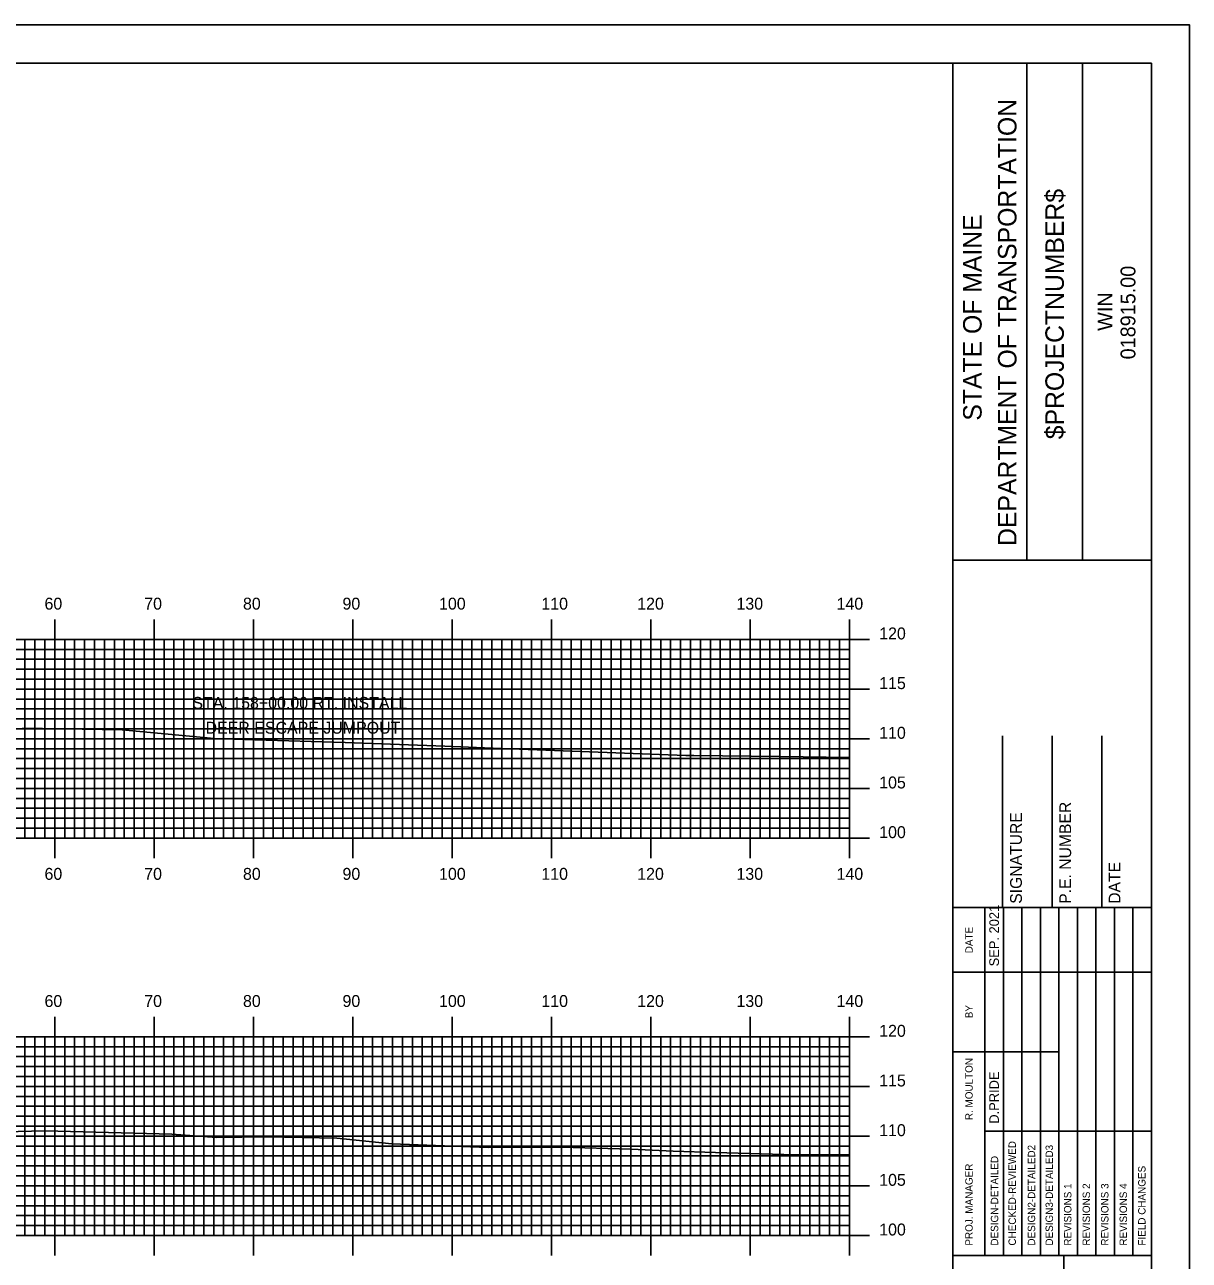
# Model space of a CAD drawing. Extents: x 1779499 to 1779842, y 442591 to 442811.
# Drawn here: x 1779721.8 to 1779839.1, y 442686.2 to 442810.5 of the extents above; entities that cross this region are included whole.
import ezdxf

# ---------------------------------------------------------------- set-up
doc = ezdxf.new("R2010")
doc.units = 0
for name, color, linetype in [('BORDER', 7, 'Continuous'), ('D_Text_Standard', 7, 'Continuous'), ('H_V ANNOTATION', 7, 'Continuous'), ('MAJOR', 7, 'Continuous'), ('MINOR', 7, 'Continuous'), ('PLOT BOUNDARY', 7, 'Continuous'), ('S_Roadway_Centerline', 7, 'Continuous')]:
    doc.layers.add(name, color=color, linetype=linetype)

msp = doc.modelspace()

# ---------------------------------------------------------------- linework, layer by layer
at = {"layer": 'BORDER'}
for p, q in [((1779815.24, 442596.67), (1779815.24, 442806.67)), ((1779822.7, 442756.66), (1779822.7, 442806.66)), ((1779828.29, 442756.66), (1779828.29, 442806.66)), ((1779815.24, 442756.65), (1779835.24, 442756.65)), ((1779820.24, 442721.67), (1779820.24, 442738.97)), ((1779825.24, 442721.67), (1779825.24, 442738.97)), ((1779830.24, 442721.67), (1779830.24, 442738.97)), ((1779815.24, 442721.67), (1779835.24, 442721.67)), ((1779815.24, 442686.67), (1779835.24, 442686.67)), ((1779826.42, 442616.67), (1779826.42, 442686.67))]:
    msp.add_line(p, q, dxfattribs=at)
msp.add_lwpolyline([(1779515.24, 442596.67), (1779835.24, 442596.67), (1779835.24, 442806.67), (1779515.24, 442806.67)], close=True, dxfattribs=at)
for points in [[(1779818.47, 442715.17), (1779818.47, 442721.67)], [(1779820.34, 442686.68), (1779820.34, 442721.67)], [(1779822.2, 442721.67), (1779822.2, 442686.68)], [(1779824.06, 442686.68), (1779824.06, 442721.67)], [(1779825.93, 442686.68), (1779825.93, 442721.67)], [(1779827.79, 442686.68), (1779827.79, 442721.67)], [(1779829.65, 442686.68), (1779829.65, 442721.67)], [(1779831.52, 442686.68), (1779831.52, 442721.67)], [(1779833.38, 442686.68), (1779833.38, 442721.67)], [(1779818.47, 442686.68), (1779818.47, 442720.26)], [(1779815.24, 442715.17), (1779835.24, 442715.17)], [(1779815.24, 442707.17), (1779818.47, 442707.17)], [(1779818.47, 442707.17), (1779825.93, 442707.17)], [(1779818.47, 442699.17), (1779835.24, 442699.17)]]:
    msp.add_lwpolyline(points, dxfattribs=at)
at = {"layer": 'MAJOR'}
for p, q in [((1779724.84, 442750.67), (1779724.84, 442748.67)), ((1779734.84, 442750.67), (1779734.84, 442748.67)), ((1779744.84, 442750.67), (1779744.84, 442748.67)), ((1779754.84, 442750.67), (1779754.84, 442748.67)), ((1779764.84, 442750.67), (1779764.84, 442748.67)), ((1779774.84, 442750.67), (1779774.84, 442748.67)), ((1779784.84, 442750.67), (1779784.84, 442748.67)), ((1779794.84, 442750.67), (1779794.84, 442748.67)), ((1779804.84, 442750.67), (1779804.84, 442748.67)), ((1779524.84, 442748.67), (1779804.84, 442748.67)), ((1779524.84, 442748.67), (1779804.84, 442748.67)), ((1779724.84, 442728.67), (1779724.84, 442748.67)), ((1779734.84, 442728.67), (1779734.84, 442748.67)), ((1779744.84, 442728.67), (1779744.84, 442748.67)), ((1779754.84, 442728.67), (1779754.84, 442748.67)), ((1779764.84, 442728.67), (1779764.84, 442748.67)), ((1779774.84, 442728.67), (1779774.84, 442748.67)), ((1779784.84, 442728.67), (1779784.84, 442748.67)), ((1779794.84, 442728.67), (1779794.84, 442748.67)), ((1779806.85, 442748.67), (1779802.84, 442748.67)), ((1779804.84, 442728.67), (1779804.84, 442748.67)), ((1779804.84, 442728.67), (1779804.84, 442748.67)), ((1779524.84, 442743.67), (1779804.84, 442743.67)), ((1779806.85, 442743.67), (1779802.84, 442743.67)), ((1779524.84, 442738.67), (1779804.84, 442738.67)), ((1779806.85, 442738.67), (1779802.84, 442738.67)), ((1779524.84, 442733.67), (1779804.84, 442733.67)), ((1779806.85, 442733.67), (1779802.84, 442733.67)), ((1779524.84, 442728.67), (1779804.84, 442728.67)), ((1779524.84, 442728.67), (1779804.84, 442728.67)), ((1779724.84, 442726.66), (1779724.84, 442728.67)), ((1779734.84, 442726.66), (1779734.84, 442728.67)), ((1779744.84, 442726.66), (1779744.84, 442728.67)), ((1779754.84, 442726.66), (1779754.84, 442728.67)), ((1779764.84, 442726.66), (1779764.84, 442728.67)), ((1779774.84, 442726.66), (1779774.84, 442728.67)), ((1779784.84, 442726.66), (1779784.84, 442728.67)), ((1779794.84, 442726.66), (1779794.84, 442728.67)), ((1779806.85, 442728.67), (1779802.84, 442728.67)), ((1779804.84, 442726.66), (1779804.84, 442728.67)), ((1779724.84, 442710.67), (1779724.84, 442708.67)), ((1779734.84, 442710.67), (1779734.84, 442708.67)), ((1779744.84, 442710.67), (1779744.84, 442708.67)), ((1779754.84, 442710.67), (1779754.84, 442708.67)), ((1779764.84, 442710.67), (1779764.84, 442708.67)), ((1779774.84, 442710.67), (1779774.84, 442708.67)), ((1779784.84, 442710.67), (1779784.84, 442708.67)), ((1779794.84, 442710.67), (1779794.84, 442708.67)), ((1779804.84, 442710.67), (1779804.84, 442708.67)), ((1779524.84, 442708.67), (1779804.84, 442708.67)), ((1779524.84, 442708.67), (1779804.84, 442708.67)), ((1779724.84, 442688.67), (1779724.84, 442708.67)), ((1779734.84, 442688.67), (1779734.84, 442708.67)), ((1779744.84, 442688.67), (1779744.84, 442708.67)), ((1779754.84, 442688.67), (1779754.84, 442708.67)), ((1779764.84, 442688.67), (1779764.84, 442708.67)), ((1779774.84, 442688.67), (1779774.84, 442708.67)), ((1779784.84, 442688.67), (1779784.84, 442708.67)), ((1779794.84, 442688.67), (1779794.84, 442708.67)), ((1779806.85, 442708.67), (1779802.84, 442708.67)), ((1779804.84, 442688.67), (1779804.84, 442708.67)), ((1779804.84, 442688.67), (1779804.84, 442708.67)), ((1779524.84, 442703.67), (1779804.84, 442703.67)), ((1779806.85, 442703.67), (1779802.84, 442703.67)), ((1779524.84, 442698.67), (1779804.84, 442698.67)), ((1779806.85, 442698.67), (1779802.84, 442698.67)), ((1779524.84, 442693.67), (1779804.84, 442693.67)), ((1779806.85, 442693.67), (1779802.84, 442693.67)), ((1779524.84, 442688.67), (1779804.84, 442688.67)), ((1779524.84, 442688.67), (1779804.84, 442688.67)), ((1779724.84, 442686.66), (1779724.84, 442688.67)), ((1779734.84, 442686.66), (1779734.84, 442688.67)), ((1779744.84, 442686.66), (1779744.84, 442688.67)), ((1779754.84, 442686.66), (1779754.84, 442688.67)), ((1779764.84, 442686.66), (1779764.84, 442688.67)), ((1779774.84, 442686.66), (1779774.84, 442688.67)), ((1779784.84, 442686.66), (1779784.84, 442688.67)), ((1779794.84, 442686.66), (1779794.84, 442688.67)), ((1779806.85, 442688.67), (1779802.84, 442688.67)), ((1779804.84, 442686.66), (1779804.84, 442688.67))]:
    msp.add_line(p, q, dxfattribs=at)
at = {"layer": 'MINOR'}
for p, q in [((1779721.84, 442728.67), (1779721.84, 442748.67)), ((1779722.84, 442728.67), (1779722.84, 442748.67)), ((1779723.84, 442728.67), (1779723.84, 442748.67)), ((1779725.84, 442728.67), (1779725.84, 442748.67)), ((1779726.84, 442728.67), (1779726.84, 442748.67)), ((1779727.84, 442728.67), (1779727.84, 442748.67)), ((1779728.84, 442728.67), (1779728.84, 442748.67)), ((1779729.84, 442728.67), (1779729.84, 442748.67)), ((1779730.84, 442728.67), (1779730.84, 442748.67)), ((1779731.84, 442728.67), (1779731.84, 442748.67)), ((1779732.84, 442728.67), (1779732.84, 442748.67)), ((1779733.84, 442728.67), (1779733.84, 442748.67)), ((1779735.84, 442728.67), (1779735.84, 442748.67)), ((1779736.84, 442728.67), (1779736.84, 442748.67)), ((1779737.84, 442728.67), (1779737.84, 442748.67)), ((1779738.84, 442728.67), (1779738.84, 442748.67)), ((1779739.84, 442728.67), (1779739.84, 442748.67)), ((1779740.84, 442728.67), (1779740.84, 442748.67)), ((1779741.84, 442728.67), (1779741.84, 442748.67)), ((1779742.84, 442728.67), (1779742.84, 442748.67)), ((1779743.84, 442728.67), (1779743.84, 442748.67)), ((1779745.84, 442728.67), (1779745.84, 442748.67)), ((1779746.84, 442728.67), (1779746.84, 442748.67)), ((1779747.84, 442728.67), (1779747.84, 442748.67)), ((1779748.84, 442728.67), (1779748.84, 442748.67)), ((1779749.84, 442728.67), (1779749.84, 442748.67)), ((1779750.84, 442728.67), (1779750.84, 442748.67)), ((1779751.84, 442728.67), (1779751.84, 442748.67)), ((1779752.84, 442728.67), (1779752.84, 442748.67)), ((1779753.84, 442728.67), (1779753.84, 442748.67)), ((1779755.84, 442728.67), (1779755.84, 442748.67)), ((1779756.84, 442728.67), (1779756.84, 442748.67)), ((1779757.84, 442728.67), (1779757.84, 442748.67)), ((1779758.84, 442728.67), (1779758.84, 442748.67)), ((1779759.84, 442728.67), (1779759.84, 442748.67)), ((1779760.84, 442728.67), (1779760.84, 442748.67)), ((1779761.84, 442728.67), (1779761.84, 442748.67)), ((1779762.84, 442728.67), (1779762.84, 442748.67)), ((1779763.84, 442728.67), (1779763.84, 442748.67)), ((1779765.84, 442728.67), (1779765.84, 442748.67)), ((1779766.84, 442728.67), (1779766.84, 442748.67)), ((1779767.84, 442728.67), (1779767.84, 442748.67)), ((1779768.84, 442728.67), (1779768.84, 442748.67)), ((1779769.84, 442728.67), (1779769.84, 442748.67)), ((1779770.84, 442728.67), (1779770.84, 442748.67)), ((1779771.84, 442728.67), (1779771.84, 442748.67)), ((1779772.84, 442728.67), (1779772.84, 442748.67)), ((1779773.84, 442728.67), (1779773.84, 442748.67)), ((1779775.84, 442728.67), (1779775.84, 442748.67)), ((1779776.84, 442728.67), (1779776.84, 442748.67)), ((1779777.84, 442728.67), (1779777.84, 442748.67)), ((1779778.84, 442728.67), (1779778.84, 442748.67)), ((1779779.84, 442728.67), (1779779.84, 442748.67)), ((1779780.84, 442728.67), (1779780.84, 442748.67)), ((1779781.84, 442728.67), (1779781.84, 442748.67)), ((1779782.84, 442728.67), (1779782.84, 442748.67)), ((1779783.84, 442728.67), (1779783.84, 442748.67)), ((1779785.84, 442728.67), (1779785.84, 442748.67)), ((1779786.84, 442728.67), (1779786.84, 442748.67)), ((1779787.84, 442728.67), (1779787.84, 442748.67)), ((1779788.84, 442728.67), (1779788.84, 442748.67)), ((1779789.84, 442728.67), (1779789.84, 442748.67)), ((1779790.84, 442728.67), (1779790.84, 442748.67)), ((1779791.84, 442728.67), (1779791.84, 442748.67)), ((1779792.84, 442728.67), (1779792.84, 442748.67)), ((1779793.84, 442728.67), (1779793.84, 442748.67)), ((1779795.84, 442728.67), (1779795.84, 442748.67)), ((1779796.84, 442728.67), (1779796.84, 442748.67)), ((1779797.84, 442728.67), (1779797.84, 442748.67)), ((1779798.84, 442728.67), (1779798.84, 442748.67)), ((1779799.84, 442728.67), (1779799.84, 442748.67)), ((1779800.84, 442728.67), (1779800.84, 442748.67)), ((1779801.84, 442728.67), (1779801.84, 442748.67)), ((1779802.84, 442728.67), (1779802.84, 442748.67)), ((1779803.84, 442728.67), (1779803.84, 442748.67)), ((1779524.84, 442747.67), (1779804.84, 442747.67)), ((1779804.84, 442747.67), (1779802.84, 442747.67)), ((1779524.84, 442746.67), (1779804.84, 442746.67)), ((1779524.84, 442745.67), (1779804.84, 442745.67)), ((1779804.84, 442746.67), (1779802.84, 442746.67)), ((1779804.84, 442745.67), (1779802.84, 442745.67)), ((1779524.84, 442744.67), (1779804.84, 442744.67)), ((1779804.84, 442744.67), (1779802.84, 442744.67)), ((1779524.84, 442742.67), (1779804.84, 442742.67)), ((1779804.84, 442742.67), (1779802.84, 442742.67)), ((1779524.84, 442741.67), (1779804.84, 442741.67)), ((1779524.84, 442740.67), (1779804.84, 442740.67)), ((1779804.84, 442741.67), (1779802.84, 442741.67)), ((1779804.84, 442740.67), (1779802.84, 442740.67)), ((1779524.84, 442739.67), (1779804.84, 442739.67)), ((1779804.84, 442739.67), (1779802.84, 442739.67)), ((1779524.84, 442737.67), (1779804.84, 442737.67)), ((1779804.84, 442737.67), (1779802.84, 442737.67)), ((1779524.84, 442736.67), (1779804.84, 442736.67)), ((1779524.84, 442735.67), (1779804.84, 442735.67)), ((1779804.84, 442736.67), (1779802.84, 442736.67)), ((1779804.84, 442735.67), (1779802.84, 442735.67)), ((1779524.84, 442734.67), (1779804.84, 442734.67)), ((1779804.84, 442734.67), (1779802.84, 442734.67)), ((1779524.84, 442732.67), (1779804.84, 442732.67)), ((1779804.84, 442732.67), (1779802.84, 442732.67)), ((1779524.84, 442731.67), (1779804.84, 442731.67)), ((1779524.84, 442730.67), (1779804.84, 442730.67)), ((1779804.84, 442731.67), (1779802.84, 442731.67)), ((1779804.84, 442730.67), (1779802.84, 442730.67)), ((1779524.84, 442729.67), (1779804.84, 442729.67)), ((1779804.84, 442729.67), (1779802.84, 442729.67)), ((1779721.84, 442688.67), (1779721.84, 442708.67)), ((1779722.84, 442688.67), (1779722.84, 442708.67)), ((1779723.84, 442688.67), (1779723.84, 442708.67)), ((1779725.84, 442688.67), (1779725.84, 442708.67)), ((1779726.84, 442688.67), (1779726.84, 442708.67)), ((1779727.84, 442688.67), (1779727.84, 442708.67)), ((1779728.84, 442688.67), (1779728.84, 442708.67)), ((1779729.84, 442688.67), (1779729.84, 442708.67)), ((1779730.84, 442688.67), (1779730.84, 442708.67)), ((1779731.84, 442688.67), (1779731.84, 442708.67)), ((1779732.84, 442688.67), (1779732.84, 442708.67)), ((1779733.84, 442688.67), (1779733.84, 442708.67)), ((1779735.84, 442688.67), (1779735.84, 442708.67)), ((1779736.84, 442688.67), (1779736.84, 442708.67)), ((1779737.84, 442688.67), (1779737.84, 442708.67)), ((1779738.84, 442688.67), (1779738.84, 442708.67)), ((1779739.84, 442688.67), (1779739.84, 442708.67)), ((1779740.84, 442688.67), (1779740.84, 442708.67)), ((1779741.84, 442688.67), (1779741.84, 442708.67)), ((1779742.84, 442688.67), (1779742.84, 442708.67)), ((1779743.84, 442688.67), (1779743.84, 442708.67)), ((1779745.84, 442688.67), (1779745.84, 442708.67)), ((1779746.84, 442688.67), (1779746.84, 442708.67)), ((1779747.84, 442688.67), (1779747.84, 442708.67)), ((1779748.84, 442688.67), (1779748.84, 442708.67)), ((1779749.84, 442688.67), (1779749.84, 442708.67)), ((1779750.84, 442688.67), (1779750.84, 442708.67)), ((1779751.84, 442688.67), (1779751.84, 442708.67)), ((1779752.84, 442688.67), (1779752.84, 442708.67)), ((1779753.84, 442688.67), (1779753.84, 442708.67)), ((1779755.84, 442688.67), (1779755.84, 442708.67)), ((1779756.84, 442688.67), (1779756.84, 442708.67)), ((1779757.84, 442688.67), (1779757.84, 442708.67)), ((1779758.84, 442688.67), (1779758.84, 442708.67)), ((1779759.84, 442688.67), (1779759.84, 442708.67)), ((1779760.84, 442688.67), (1779760.84, 442708.67)), ((1779761.84, 442688.67), (1779761.84, 442708.67)), ((1779762.84, 442688.67), (1779762.84, 442708.67)), ((1779763.84, 442688.67), (1779763.84, 442708.67)), ((1779765.84, 442688.67), (1779765.84, 442708.67)), ((1779766.84, 442688.67), (1779766.84, 442708.67)), ((1779767.84, 442688.67), (1779767.84, 442708.67)), ((1779768.84, 442688.67), (1779768.84, 442708.67)), ((1779769.84, 442688.67), (1779769.84, 442708.67)), ((1779770.84, 442688.67), (1779770.84, 442708.67)), ((1779771.84, 442688.67), (1779771.84, 442708.67)), ((1779772.84, 442688.67), (1779772.84, 442708.67)), ((1779773.84, 442688.67), (1779773.84, 442708.67)), ((1779775.84, 442688.67), (1779775.84, 442708.67)), ((1779776.84, 442688.67), (1779776.84, 442708.67)), ((1779777.84, 442688.67), (1779777.84, 442708.67)), ((1779778.84, 442688.67), (1779778.84, 442708.67)), ((1779779.84, 442688.67), (1779779.84, 442708.67)), ((1779780.84, 442688.67), (1779780.84, 442708.67)), ((1779781.84, 442688.67), (1779781.84, 442708.67)), ((1779782.84, 442688.67), (1779782.84, 442708.67)), ((1779783.84, 442688.67), (1779783.84, 442708.67)), ((1779785.84, 442688.67), (1779785.84, 442708.67)), ((1779786.84, 442688.67), (1779786.84, 442708.67)), ((1779787.84, 442688.67), (1779787.84, 442708.67)), ((1779788.84, 442688.67), (1779788.84, 442708.67)), ((1779789.84, 442688.67), (1779789.84, 442708.67)), ((1779790.84, 442688.67), (1779790.84, 442708.67)), ((1779791.84, 442688.67), (1779791.84, 442708.67)), ((1779792.84, 442688.67), (1779792.84, 442708.67)), ((1779793.84, 442688.67), (1779793.84, 442708.67)), ((1779795.84, 442688.67), (1779795.84, 442708.67)), ((1779796.84, 442688.67), (1779796.84, 442708.67)), ((1779797.84, 442688.67), (1779797.84, 442708.67)), ((1779798.84, 442688.67), (1779798.84, 442708.67)), ((1779799.84, 442688.67), (1779799.84, 442708.67)), ((1779800.84, 442688.67), (1779800.84, 442708.67)), ((1779801.84, 442688.67), (1779801.84, 442708.67)), ((1779802.84, 442688.67), (1779802.84, 442708.67)), ((1779803.84, 442688.67), (1779803.84, 442708.67)), ((1779524.84, 442707.67), (1779804.84, 442707.67)), ((1779804.84, 442707.67), (1779802.84, 442707.67)), ((1779524.84, 442706.67), (1779804.84, 442706.67)), ((1779804.84, 442706.67), (1779802.84, 442706.67)), ((1779524.84, 442705.67), (1779804.84, 442705.67)), ((1779524.84, 442704.67), (1779804.84, 442704.67)), ((1779804.84, 442705.67), (1779802.84, 442705.67)), ((1779804.84, 442704.67), (1779802.84, 442704.67)), ((1779524.84, 442702.67), (1779804.84, 442702.67)), ((1779804.84, 442702.67), (1779802.84, 442702.67)), ((1779524.84, 442701.67), (1779804.84, 442701.67)), ((1779804.84, 442701.67), (1779802.84, 442701.67)), ((1779524.84, 442700.67), (1779804.84, 442700.67)), ((1779524.84, 442699.67), (1779804.84, 442699.67)), ((1779804.84, 442700.67), (1779802.84, 442700.67)), ((1779804.84, 442699.67), (1779802.84, 442699.67)), ((1779524.84, 442697.67), (1779804.84, 442697.67)), ((1779804.84, 442697.67), (1779802.84, 442697.67)), ((1779524.84, 442696.67), (1779804.84, 442696.67)), ((1779804.84, 442696.67), (1779802.84, 442696.67)), ((1779524.84, 442695.67), (1779804.84, 442695.67)), ((1779524.84, 442694.67), (1779804.84, 442694.67)), ((1779804.84, 442695.67), (1779802.84, 442695.67)), ((1779804.84, 442694.67), (1779802.84, 442694.67)), ((1779524.84, 442692.67), (1779804.84, 442692.67)), ((1779804.84, 442692.67), (1779802.84, 442692.67)), ((1779524.84, 442691.67), (1779804.84, 442691.67)), ((1779804.84, 442691.67), (1779802.84, 442691.67)), ((1779524.84, 442690.67), (1779804.84, 442690.67)), ((1779524.84, 442689.67), (1779804.84, 442689.67)), ((1779804.84, 442690.67), (1779802.84, 442690.67)), ((1779804.84, 442689.67), (1779802.84, 442689.67))]:
    msp.add_line(p, q, dxfattribs=at)
at = {"layer": 'PLOT BOUNDARY'}
msp.add_lwpolyline([(1779499.06, 442590.55), (1779839.06, 442590.55), (1779839.06, 442810.55), (1779499.06, 442810.55)], close=True, dxfattribs=at)
at = {"layer": 'S_Roadway_Centerline'}
for points in [[(1779721.59, 442739.75), (1779731.64, 442739.56), (1779740.89, 442738.71), (1779744.98, 442738.55), (1779754.07, 442738.28), (1779764.12, 442737.93), (1779768.1, 442737.74), (1779788.36, 442737), (1779789.17, 442736.99), (1779797.83, 442736.89), (1779804.84, 442736.79)], [(1779712.94, 442698.94), (1779723.89, 442699.2), (1779736.64, 442698.88), (1779741.12, 442698.53), (1779746.21, 442698.6), (1779753.25, 442698.47), (1779758.78, 442697.91), (1779768.47, 442697.52), (1779775.84, 442697.57), (1779782.88, 442697.37), (1779787.11, 442697.15), (1779791.35, 442697.03), (1779799.38, 442696.8), (1779804.84, 442696.79)]]:
    msp.add_lwpolyline(points, dxfattribs=at)

# ---------------------------------------------------------------- texts
at = {"layer": 'BORDER'}
for s, height, p in [('DEPARTMENT OF TRANSPORTATION', 1.8635, (1779821.66, 442758.08)), ('$PROJECTNUMBER$', 1.8635, (1779826.43, 442768.82)), ('STATE OF MAINE', 1.8635, (1779818.15, 442770.69)), ('018915.00', 1.491, (1779833.63, 442776.86)), ('WIN', 1.491, (1779831.32, 442779.73)), ('P.E. NUMBER', 1.1811, (1779827.16, 442722.06)), ('SIGNATURE', 1.181, (1779822.2, 442722.06)), ('DATE', 1.181, (1779832.12, 442722.06)), ('SEP. 2021', 0.969, (1779819.89, 442715.76)), ('DATE', 0.743, (1779817.25, 442717.08)), ('BY', 0.743, (1779817.25, 442710.54)), ('R. MOULTON', 0.745, (1779817.25, 442700.28)), ('D.PRIDE', 0.969, (1779819.89, 442699.92)), ('CHECKED-REVIEWED', 0.7455, (1779821.6, 442687.65)), ('DESIGN2-DETAILED2', 0.7455, (1779823.54, 442687.65)), ('DESIGN3-DETAILED3', 0.7455, (1779825.33, 442687.65)), ('PROJ. MANAGER', 0.7455, (1779817.25, 442687.65)), ('DESIGN-DETAILED', 0.7455, (1779819.82, 442687.65)), ('FIELD CHANGES', 0.7455, (1779834.65, 442687.65)), ('REVISIONS 1', 0.7455, (1779827.19, 442687.65)), ('REVISIONS 2', 0.7455, (1779829.06, 442687.65)), ('REVISIONS 3', 0.7455, (1779830.92, 442687.65)), ('REVISIONS 4', 0.7455, (1779832.78, 442687.65))]:
    msp.add_text(s, height=height, rotation=90, dxfattribs=at).set_placement(p)
at = {"layer": 'D_Text_Standard'}
for s, p in [('STA. 158+00.00 RT. INSTALL ', (1779738.7, 442741.68)), ('DEER ESCAPE JUMPOUT', (1779740.02, 442739.18))]:
    msp.add_text(s, height=1.2, dxfattribs=at).set_placement(p)
at = {"layer": 'H_V ANNOTATION'}
for s, p in [('60', (1779723.81, 442751.67)), ('70', (1779733.85, 442751.67)), ('80', (1779743.79, 442751.67)), ('90', (1779753.81, 442751.67)), ('100', (1779763.53, 442751.67)), ('110', (1779773.83, 442751.67)), ('120', (1779783.48, 442751.67)), ('130', (1779793.47, 442751.67)), ('140', (1779803.55, 442751.67)), ('120', (1779807.84, 442748.67)), ('115', (1779807.84, 442743.67)), ('110', (1779807.84, 442738.67)), ('105', (1779807.84, 442733.67)), ('100', (1779807.84, 442728.67)), ('60', (1779723.81, 442724.47)), ('70', (1779733.85, 442724.47)), ('80', (1779743.79, 442724.47)), ('90', (1779753.81, 442724.47)), ('100', (1779763.53, 442724.47)), ('110', (1779773.83, 442724.47)), ('120', (1779783.48, 442724.47)), ('130', (1779793.47, 442724.47)), ('140', (1779803.55, 442724.47)), ('60', (1779723.81, 442711.67)), ('70', (1779733.85, 442711.67)), ('80', (1779743.79, 442711.67)), ('90', (1779753.81, 442711.67)), ('100', (1779763.53, 442711.67)), ('110', (1779773.83, 442711.67)), ('120', (1779783.48, 442711.67)), ('130', (1779793.47, 442711.67)), ('140', (1779803.55, 442711.67)), ('120', (1779807.84, 442708.67)), ('115', (1779807.84, 442703.67)), ('110', (1779807.84, 442698.67)), ('105', (1779807.84, 442693.67)), ('100', (1779807.84, 442688.67))]:
    msp.add_text(s, height=1.2, dxfattribs=at).set_placement(p)

doc.saveas('drawing.dxf')
